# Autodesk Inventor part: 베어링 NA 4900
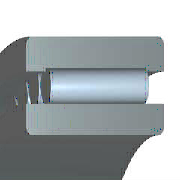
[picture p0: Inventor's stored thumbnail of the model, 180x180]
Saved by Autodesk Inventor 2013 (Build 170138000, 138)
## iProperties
Created: 2014-07
Part Number: 베어링 NA 4900
Material: Steel, Mild
Description: 니들 롤러 베어링 - 경계 치수 및 공차
Document SubType Name: Modeling
Standard: KS B 2029
Designer: KYOUNG IL JANG
Standards Organization: KS
Language: ko-KR
Size Designation: NA 4900 - 10 x 22 x 13
Categories: <MemberInstance><Categories><Category DisplayName="샤프트 부품" InternalName="7f7aeb1f-a693-4053-b835-cee3144e0d98" Mnemonic="SHFT"><Category DisplayName="베어링" Inter
Density: 7.86 g/cm^3
Mass: 23.8214 g
Surface Area: 38.613 cm^2
Volume: 3.03071 cm^3
Company: 한국ATC센터
IsCustomPart: 0
Author: KYOUNG IL JANG
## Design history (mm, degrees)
sketch "스케치"
  geometry: L1 (1.857, 9)-(11.143, 9); L2 (11.143, 9)-(11.143, 7); L3 (13, 7)-(0, 7); L4 (1.857, 7)-(1.857, 9); L5 (1.857, 8)-(11.143, 8); L6 (6.5, 8)-(6.5, 7); L7 (0, 5)-(13, 5); L8 (0, 11)-(13, 11); L9 (13, 5)-(13, 7); L10 (13, 8.8)-(13, 11); L11 (1.857, 8.8)-(0, 8.8); L12 (11.143, 8.8)-(13, 8.8); L13 (-6, 0)-(36, 0) reference; L14 (0, -1.9)-(0, 14.9) reference
  constraints: 24 end point, 8 point on line, 3 midpoint, 3 parallel, 3 perpendicular, 2 symmetric about line, 1 horizontal, 1 other
  dimensions: "d6" = 10 diameter of L7 L13 (= WD); "d7" = 14 diameter of L3 L13 (= KID1); "d8" = 22 diameter of L8 L13 (= BD); "d9" = 16 diameter of L6.start L13 (= 0.5 x WD + 0.5 x BD); "d10" = 17.6 diameter of L12 L13 (= 0.9 x BD + 0.9 x WD - 0.8 x KID1); "d11" = 18 diameter of L1 L13 (= BD + WD - KID1); "d12" = 1.85714 distance between parallel lines of L14 L4 (= 0.142857 x KB); "d13" = 13 distance between parallel lines of L14 L9 (= KB); "d14" = 11.14286 distance between parallel lines of L14 L2 (= 0.857143 x KB)
revolve "본체" stored, may be unused: angle "d17" = 90 deg
revolve "롤러" stored, may be unused: angle "d18" = 90 deg
pattern_circular "IDS_ARRAYROLLER[SIMPL:T]" dims angle "d2" = 360 deg
body "Solid1"
fillet "모깎기1" dims "d0" = 0.3 (= KRS)
other parameters: "WD" = 10 [user parameter; used in 6 equation terms], "BD" = 22 [user parameter; used in 6 equation terms], "KB" = 13 [user parameter; used in 3 equation terms], "KID1" = 14 [user parameter; used in 4 equation terms], "KRS" = 0.3 [user parameter; used in 1 equation term], "d3" = 0, "d4" = 0, "d5" = 0, "d15" = 0, "d16" = 0, "BC0" = 9150000 [user parameter], "WR" = 5 (= 0.5 x WD) [user parameter], "BBA" = 0 [user parameter], "BC" = 8150000 [user parameter], "BR" = 11 (= 0.5 x BD) [user parameter]
